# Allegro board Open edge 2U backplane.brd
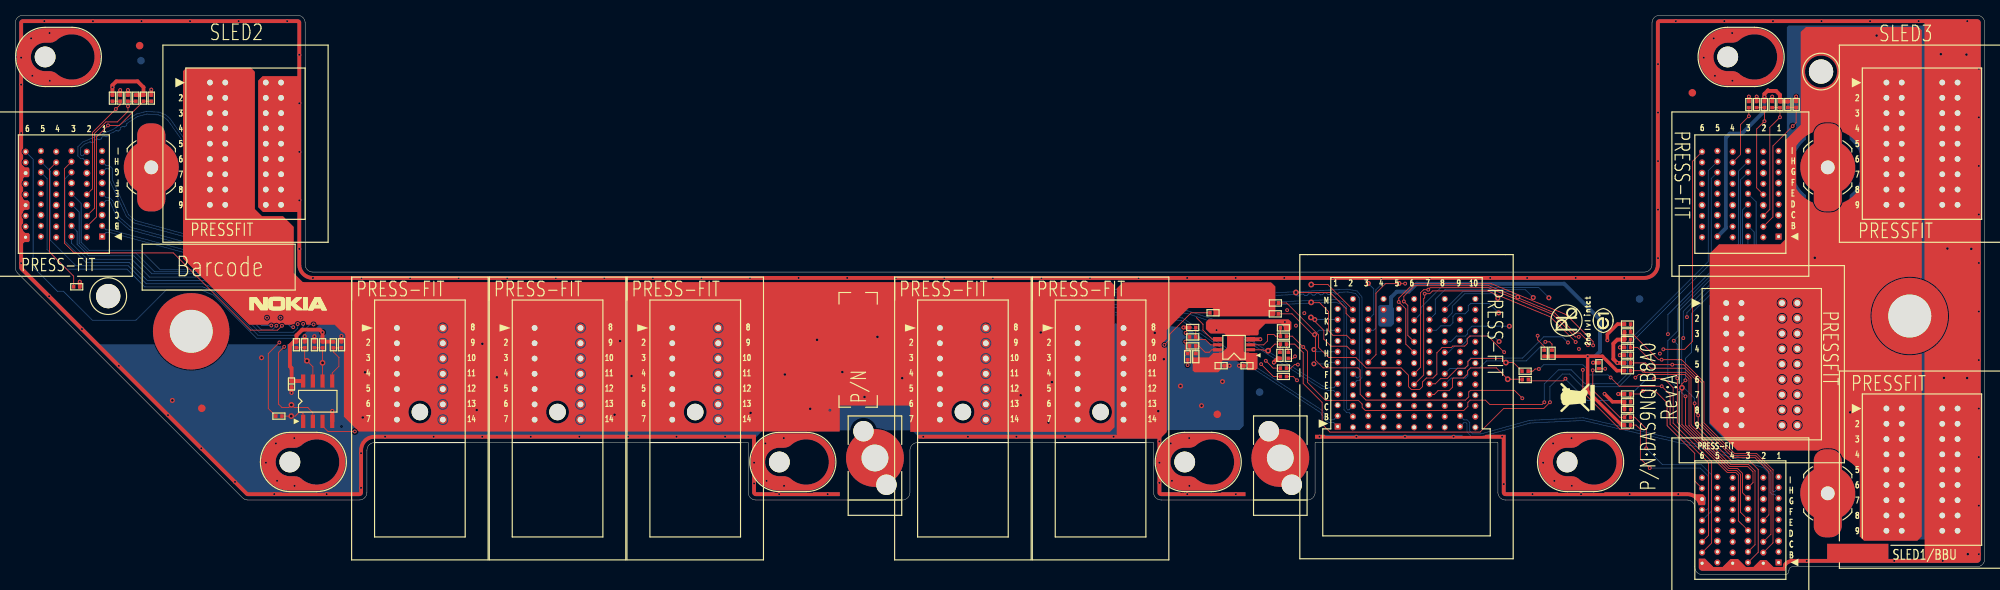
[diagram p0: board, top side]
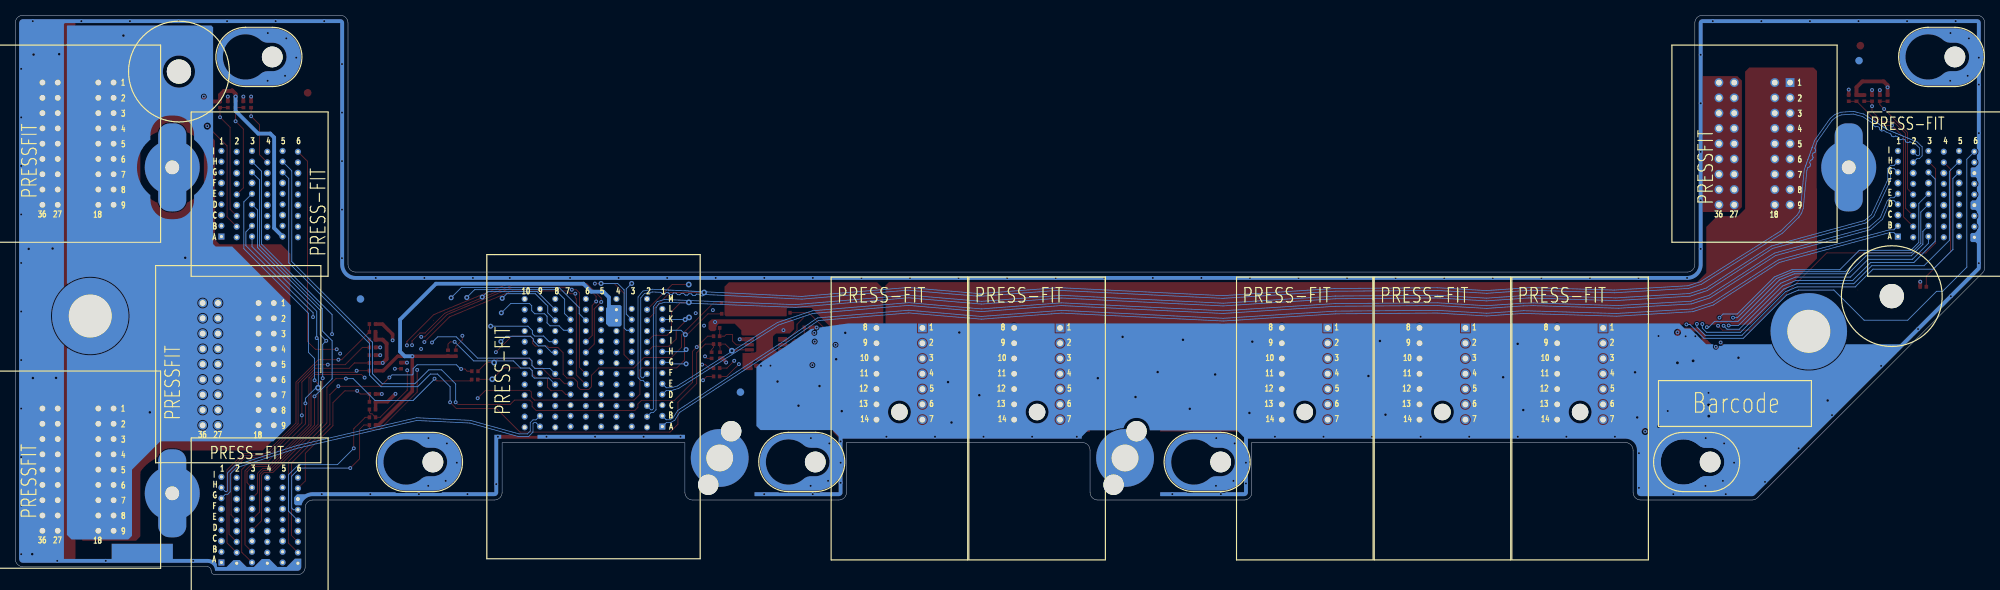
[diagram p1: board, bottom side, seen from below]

Outline 257.5 x 73.2 mm; copper layers: TOP, GND, IN1, VCC, VCC1, IN2, GND1, BOTTOM. Coordinates in mm from the lower left corner of the outline.
Outline path: 0,72.2 0,40.19 arc(0.08,39.81) 0.29,39.48 29.71,10.07 arc(30.03,9.85) 30.41,9.77 44.98,9.77 arc(45.68,10.07) 45.98,10.77 45.98,16.29 arc(46.27,17) 46.98,17.29 95.83,17.29 95.83,10.77 arc(96.12,10.07) 96.83,9.77 115.97,9.77 arc(116.68,10.07) 116.97,10.77 116.97,16.29 arc(117.27,17) 117.98,17.29 148.82,17.29 148.82,10.77 arc(149.12,10.07) 149.82,9.77 168.95,9.77 arc(169.66,10.07) 169.95,10.77 169.95,17.28 193.85,17.28 193.85,10.77 arc(194.14,10.07) 194.85,9.77 218.6,9.77 arc(219.31,9.48) 219.6,8.77 219.6,1 arc(219.89,0.29) 220.6,0 231.4,0 arc(231.75,0.15) 231.9,0.5 231.9,0.55 arc(232.05,0.9) 232.4,1.05 256.5,1.05 arc(257.21,1.34) 257.5,2.05 257.5,72.2 arc(257.21,72.91) 256.5,73.2 215,73.2 arc(214.29,72.91) 214,72.2 214,40.6 arc(213.71,39.89) 213,39.6 38.9,39.6 arc(38.19,39.89) 37.9,40.6 37.9,72.2 arc(37.61,72.91) 36.9,73.2 1,73.2 arc(0.29,72.91) 0,72.2

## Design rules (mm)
constraint set DEFAULT: min track width 0.114
net group RESET: nets IRQ_RMC_ALERT_N TP_BUF_EN
net group SMB_BBU_ALERT_N: nets SMB_BBU_ALERT_N SMB_BBU_ALERT_R_N
net group SMB_PMBUS_BBU_SCL: nets SMB_PMBUS_BBU_SCL SMB_PMBUS_SCL
net group SMB_PMBUS_BBU_SDA: nets SMB_PMBUS_BBU_SDA SMB_PMBUS_SDA
net group SMB_SLED_BUF_SDA: nets SMB_SLED_BUF_SDA SMB_SLED_BUF_SDA_R
net group LAN: nets LAN_SLED1_MDIN1 LAN_SLED1_MDIP1 LAN_SLED2_MDIN3 LAN_SLED2_MDIP3
net group P3V3_SLED1: nets P3V3_SLED1 SB_SLED1_ADDR_0 SB_SLED1_ADDR_1 SB_SLED1_ADDR_2
net group P3V3_SLED2: nets P3V3_SLED2 SB_SLED2_ADDR_0 SB_SLED2_ADDR_1 SB_SLED2_ADDR_2
net group P3V3_SLED3: nets P3V3_SLED3 SB_SLED3_ADDR_0 SB_SLED3_ADDR_1 SB_SLED3_ADDR_2
net group SMB_SLED_BUF_SCL: nets SMB_SLED_BUF_SCL SMB_SLED_BUF_SCL_R SMB_SLED_BUF_SCL_R1
net group SMB_SLED_COMBINE_SCL: nets SMB_3UBP_TEMP_SCL SMB_SLED_COMBINE_SCL SMB_SLED_COMBINE_SCL_R SMB_SLED_COMBINE_SCL_R1
net group SMB_SLED_COMBINE_SDA: nets SMB_3UBP_TEMP_SDA SMB_SLED_COMBINE_SDA SMB_SLED_COMBINE_SDA_R SMB_SLED_COMBINE_SDA_R1

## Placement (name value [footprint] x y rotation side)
C1045  0.1UF  [C0402]  36.12 24.96 270 top
C1375  0.1UF  [C0402]  157.66 27.35 0 top
C1377  0.1UF  [C0402]  161.05 27.34 180 top
DM2  -  [WEEE]  206.52 21.52 90 top
DM3  -  [PB-E1_SMALL]  202.82 33.26 90 top
DM4  -  [PNLABEL_15X5]  112.7 21.92 90 top
DM6  -  [PCB_VENDOR_LOGO_15X8]  106.51 21.53 90 top
DM7  -  [BARCODE_20X6]  42.66 19.4 180 bottom
DM8  -  [BARCODE_20X6]  16.59 37.24 0 top
H1  -  [HOLE_C10D5-6B10_NPB]  247.7 33.85 0 top
H2  -  [HOLE_C10D5-6B10_NPB]  23 31.85 0 top
H5  -  [HOLE_C7-5D2-7_4-9B7-5_OB3-5XC3-75N_NPM]  3.9 67.75 90 top
H6  -  [HOLE_C7-5D2-7_4-9B7-5_OB3-5XC3-75N_NPM]  35.9 14.75 90 top
H9  -  [HOLE_C7-5D2-7_4-9B7-5_OB3-5XC3-75N_NPM]  223.9 67.75 90 top
H10  -  [HOLE_C7-5D2-7_4-9B7-5_OB3-5XC3-75N_NPM]  99.9 14.75 90 top
H11  -  [HOLE_C7-5D2-7_4-9B7-5_OB3-5XC3-75N_NPM]  152.9 14.75 90 top
H12  -  [HOLE_C7-5D2-7_4-9B7-5_OB3-5XC3-75N_NPM]  202.9 14.75 90 top
H13  -  [HOLE_TOOLINGD125N_T2-0]  12.15 36.45 0 top
H14  -  [HOLE_TOOLINGD125N_T2-0]  236.1 65.83 0 top
J2  -  [HSD_F36D9_P2_LUV]  244.65 21.75 0 top
J3  -  [HSD_F36D9_P2_LUV]  223.7 35.55 0 top
J4  -  [HSD_F36D9_P2_LUV]  25.45 64.4 0 top
J5  -  [HSD_F36D9_P2_LUV]  244.65 64.4 0 top
J7  -  [HSD_F54D6_P2W1-4_RDH]  230.55 1.6 180 top
J8  -  [HSD_M120D10H5D_P2W1-4_LDH]  172.9 19.39 180 top
J9  -  [HSD_F54D6_P2W1-4_RDH]  11.35 44.25 180 top
J10  -  [HSD_F54D6_P2W1-4_RDH]  230.55 44.25 180 top
J37  -  [CON_GUIDE-M1XE]  17.78 53.3 0 top
J39  -  [CON_GUIDE-M1XE]  236.98 10.65 0 top
J40  -  [CON_GUIDE-M1XE]  236.98 53.3 0 top
JP1  -  [HSD_M14]  85.9 32.29 0 top
JP2  -  [HSD_M14]  120.9 32.29 0 top
JP3  -  [HSD_M14]  67.9 32.29 0 top
JP4  -  [HSD_M14]  138.9 32.29 0 top
JP5  -  [CON_GUIDE-FXC]  112.4 15.28 0 top
JP6  -  [CON_GUIDE-FXC]  165.4 15.28 0 top
JP7  -  [HSD_M14]  49.9 32.29 0 top
NOREF  -  []  152.9 14.75 0 top
NOREF#2  -  []  0 72.2 0 top
NOREF#3  -  []  252.47 360.99 0 top
NOREF#4  -  []  152.9 14.75 0 top
NOREF#5  -  []  112.4 15.28 0 top
NOREF#6  -  []  23 31.85 0 top
NOREF#7  -  []  202.9 14.75 0 top
NOREF#8  -  []  322.16 7.18 0 top
NOREF#9  -  []  0 154 270 top
NOREF#10  -  []  202.9 14.75 0 top
NOREF#11  -  []  247.7 33.85 0 top
NOREF#12  -  []  236.98 10.65 0 top
NOREF#13  -  []  236.98 53.3 0 top
NOREF#14  -  []  0 160 0 top
NOREF#15  -  []  257.5 -5.6 270 top
NOREF#16  -  []  223.9 67.75 0 top
NOREF#17  -  []  3.9 67.75 0 top
NOREF#18  -  []  257.5 154 270 top
NOREF#19  -  []  17.78 53.3 0 top
NOREF#20  -  []  255.5 -13.6 90 top
NOREF#21  -  []  0 0 0 top
NOREF#22  -  [unnamed#2]  16.26 69.23 0 top
NOREF#23  -  [unnamed#2]  157.16 20.99 0 top
NOREF#24  -  [unnamed#2]  219.27 63.06 0 top
NOREF#25  -  []  236.98 10.65 0 top
NOREF#26  -  []  0 -5.6 270 top
NOREF#27  -  []  99.9 14.75 0 top
NOREF#28  -  []  165.4 15.28 0 top
NOREF#29  -  [unnamed#2]  24.38 21.77 0 top
NOREF#30  -  []  99.9 14.75 0 top
NOREF#31  -  []  23 31.85 0 top
NOREF#32  -  []  236.98 53.3 0 top
NOREF#33  -  []  17.78 53.3 0 top
NOREF#34  -  []  247.7 33.85 0 top
NOREF#35  -  []  165.4 15.28 0 top
NOREF#36  -  []  0 0 0 top
NOREF#37  -  []  223.9 67.75 0 top
NOREF#38  -  []  3.9 67.75 0 top
NOREF#39  -  []  231.4 0 90 top
NOREF#40  -  [unnamed#2]  212.37 36.07 180 bottom
NOREF#41  -  [unnamed#2]  162.69 23.89 180 bottom
NOREF#42  -  [unnamed#2]  16.43 67.26 180 bottom
R1  4.7K  [R0402]  15.75 62.36 270 top
R2  4.7K  [R0402]  228.7 61.52 270 top
R3  33  [R0402]  166.45 28.71 270 top
R4  33  [R0402]  165.81 25.94 0 top
R5  33  [R0402]  165.81 27.03 0 top
R8  4.7K  [R0402]  16.76 62.36 270 top
R9  1K  [R0402]  17.78 62.36 90 top
R10  4.7K  [R0402]  231.76 61.53 270 top
R11  1K  [R0402]  232.85 61.53 90 top
R12  4.7K  [R0402]  230.73 61.52 270 top
R13  4.7K  [R0402]  210.8 30.76 0 top
R14  4.7K  [R0402]  12.7 62.36 270 top
R15  4.7K  [R0402]  210.8 27.71 0 top
R19  1K  [R0402]  14.73 62.36 90 top
R20  1K  [R0402]  229.71 61.52 90 top
R21  1K  [R0402]  210.8 29.74 180 top
R22  1K  [R0402]  13.72 62.36 90 top
R23  1K  [R0402]  227.68 61.52 90 top
R24  1K  [R0402]  210.8 28.73 180 top
R29  4.7K  [R0402]  210.8 19.58 0 top
R31  4.7K  [R0402]  210.8 22.63 0 top
R32  1K  [R0402]  210.8 23.65 180 top
R34  4.7K  [R0402]  200.92 28.98 90 top
R35  4.7K  [R0402]  199.91 28.98 90 top
R36  4.7K  [R0402]  210.8 26.7 0 top
R37  4.7K  [R0402]  210.8 21.62 0 top
R38  0  [R0402]  210.8 20.6 0 top
R39  33  [R0402]  197.43 25.53 0 top
R40  33  [R0402]  197.41 26.63 0 top
R41  100  [R0402]  164.74 34.13 180 top
R42  100  [R0402]  156.6 34.28 0 top
R43  100  [R0402]  164.76 35.56 180 top
R46  0  [R0402]  153.95 29.94 0 top
R47  33  [R0402]  153.95 31.12 0 top
R48  4.7K  [R0402]  154.35 28.53 90 top
R49  4.7K  [R0402]  153.95 32.35 0 top
R50  4.7K  [R0402]  165.35 28.71 90 top
R51  4.7K  [R0402]  165.81 32.3 180 top
R52  33  [R0402]  165.81 30.17 0 top
R53  33  [R0402]  165.81 31.21 0 top
R54  0  [R0402]  207.07 27.35 90 top
R55  0  [R0402]  8.03 37.68 0 top
R56  0  [R0402]  226.67 61.52 90 top
R1102  4.7K  [R0402]  41.59 30.09 270 top
R1103  100  [R0402]  42.65 30.09 90 top
R1108  4.7K  [R0402]  40.17 30.09 270 top
R1109  100  [R0402]  39.11 30.09 90 top
R1113  4.7K  [R0402]  36.76 30.09 270 top
R1114  100  [R0402]  37.84 30.09 90 top
R1122  33.2  [R0402]  34.47 20.75 180 top
R1123  33.2  [R0402]  153.28 28.53 90 top
R2297  4.7K  [R0402]  210.8 31.78 0 top
R2298  1K  [R0402]  210.8 32.79 180 top
U31  -  [SOIC8]  39.54 22.7 90 top
U118  -  [TSSOP8_3XB]  159.35 29.76 180 top

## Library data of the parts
C1045 = Q_CAP: alternate symbols: (C0402_OCTAGONXA,C0402-0201); part number: Q_CAP_0402-0.1UF,25V,10%,X7R,CH4104K1B00; tolerance: 10%; signal model: DEFAULT_CAPACITOR_100000pF_2_1
C1375 C1377 = Q_CAP: alternate symbols: (C0402_OCTAGONXA,C0402-0201); part number: Q_CAP_0402-0.1UF,25V,10%,X7R,CH4104K1B00; tolerance: 10%
DM2 = DUMMY_SYMBOL: part number: DUMMY_SYMBOL-WEEE,MECH,EMPTY,DUMMY2
DM3 = DUMMY_SYMBOL: part number: DUMMY_SYMBOL-PB-E1_SMALL,MECH,EMPTY,DUMMY3
DM4 = DUMMY_SYMBOL: part number: DUMMY_SYMBOL-PCBA_LABEL_15X5,MECH,MECH,DUMMY4
DM6 = DUMMY_SYMBOL: part number: DUMMY_SYMBOL-PCB_VENDOR_LOGO_15X8,MECH,EMPTY,DUMMY7
DM7 DM8 = DUMMY_SYMBOL: part number: DUMMY_SYMBOL-BARCODE_20X6,MECH,MECH,DUMMY15
H1 H2 = HOLE: part number: HOLE_TH-EMPTY,HOLE596
H5 H6 H9-H12 = HOLE: part number: HOLE_TH-EMPTY,HOLE1056
H13 H14 = HOLE: part number: HOLE_TH-EMPTY,DUMMY50
J2-J5 = CONN36_10078768001LHLF: part number: CONN36_10078768001LHLF-CONN36_10078768-001LHLF,THLF,IO,DFHS36FS123
J7 J9 J10 = CONN54_10130665102LF: part number: CONN54_10130665102LF-CONN54_10130665-102LF,THLF,IO,DFHS54FS008
J8 = CONN120_10124150102LF: part number: CONN120_10124150102LF-CONN120_10124150-102LF,THLF,IO,DFHDC0MR005
J37 J39 J40 = CONN1_D11402200000Z1: part number: CONN1_D11402200000Z1-CONN1_D11402-200000-Z1,THLF,IO,DFHD01MS073
JP1-JP4 JP7 = CONN14_10028918001LF: part number: CONN14_10028918001LF-CONN14_10028918001LF,THLF,IO,DFPJ14MR000
JP5 JP6 = CONN1_D11403000A00Z1: part number: CONN1_D11403000A00Z1-CONN1_D11403-000A00-Z1,THLF,IO,DFHS03FR014
R1 R10 R12 R29 R34-R37 R1102 R1108 R2297 = Q_RES: alternate symbols: (R0402-0201); part number: Q_RES_0402LF-4.7K,1%,1/16W,CHIP,CS24702FB10; tolerance: 1%; signal model: DEFAULT_RESISTOR_4700OHM_2_1
R2 R8 R13-R15 R31 R1113 = Q_RES: alternate symbols: (R0402-0201); part number: Q_RES_0402LF-4.7K,1%,1/16W,EMPTY,CS24702FB10; tolerance: 1%; signal model: DEFAULT_RESISTOR_4700OHM_2_1
R3-R5 = Q_RES: alternate symbols: (R0402-0201); part number: Q_RES_0402LF-33       ,1%  ,1/16W,CHIP,CS03302FB19; tolerance: 1%; signal model: Q_RES_0402LF-33________1%___1/A_33
R9 R21-R24 R32 = Q_RES: alternate symbols: (R0402-0201); part number: Q_RES_0402LF-1K,1%,1/16W,CHIP,TMP_QCS21002FB24; tolerance: 1%; signal model: DEFAULT_RESISTOR_1000.000000OHM_2_1
R11 R19 R20 R2298 = Q_RES: alternate symbols: (R0402-0201); part number: Q_RES_0402LF-1K,1%,1/16W,EMPTY,TMP_QCS21002FB24; tolerance: 1%; signal model: DEFAULT_RESISTOR_1000.000000OHM_2_1
R38 = Q_RES: alternate symbols: (R0402-0201); part number: Q_RES_0402LF-0,5%,1/16W,CHIP,CS00002JB38; tolerance: 5%; signal model: DEFAULT_RESISTOR_0.001OHM_2_1
R39 R40 = Q_RES: alternate symbols: (R0402-0201); part number: Q_RES_0402LF-33       ,1%  ,1/16W,CHIP,CS03302FB19; tolerance: 1%; signal model: DEFAULT_RESISTOR_0.001OHM_2_1
R41-R43 = Q_RES: alternate symbols: (R0402-0201); part number: Q_RES_0402LF-100,1%,1/16W,CHIP,TMP_QCS11002FB22; tolerance: 1%
R46 = Q_RES: alternate symbols: (R0402-0201); part number: Q_RES_0402LF-0,5%,1/16W,CHIP,CS00002JB38; tolerance: 5%; signal model: Q_RES_0402LF-0_5%_1/16W_CHIP_CA_0
R47 R52 R53 = Q_RES: alternate symbols: (R0402-0201); part number: Q_RES_0402LF-33       ,1%  ,1/16W,CHIP,CS03302FB19; tolerance: 1%; signal model: Q_RES_0402LF-0_5%_1/16W_CHIP_CA_0
R48 R49 = Q_RES: alternate symbols: (R0402-0201); part number: Q_RES_0402LF-4.7K,1%,1/16W,EMPTY,CS24702FB10; tolerance: 1%
R50 R51 = Q_RES: alternate symbols: (R0402-0201); part number: Q_RES_0402LF-4.7K,1%,1/16W,CHIP,CS24702FB10; tolerance: 1%
R54-R56 = Q_RES: alternate symbols: (R0402-0201); part number: Q_RES_0402LF-0,5%,1/16W,CHIP,CS00002JB38; tolerance: 5%
R1103 R1109 = Q_RES: alternate symbols: (R0402-0201); part number: Q_RES_0402LF-100,1%,1/16W,EMPTY,TMP_QCS11002FB22; tolerance: 1%; signal model: DEFAULT_RESISTOR_100OHM_2_1
R1114 = Q_RES: alternate symbols: (R0402-0201); part number: Q_RES_0402LF-100,1%,1/16W,CHIP,TMP_QCS11002FB22; tolerance: 1%; signal model: DEFAULT_RESISTOR_100OHM_2_1
R1122 R1123 = Q_RES: alternate symbols: (R0402-0201); part number: Q_RES_0402LF-33.2,1%,1/16W,CHIP,CS03322FB34; tolerance: 1%; signal model: Q_RES_0402LF-33.2_1%_1/16W_CHIA_33.2
U31 = TMP75AIDR: part number: TMP75AIDR-TMP75AIDR,SMLF,IC,AL000075061
U118 = PCA9617ADP: part number: PCA9617ADP-PCA9617ADP,SMLF,IC,AL009617K02

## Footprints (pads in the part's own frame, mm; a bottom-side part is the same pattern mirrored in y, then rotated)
BARCODE_20X6
  round 0.102 smd: 1(0,0)
C0402
  rect 0.457x0.508 smd: 1(-0.4,0) 2(0.4,0)
CON_GUIDE-FXC
  round 2.667 hole 2.667 unplated: (-1.5,3.5) (1.5,-3.5)
  round 7.569 hole 3.505: SCR_G1(0,0)
CON_GUIDE-M1XE
  custom 1.798x1.798 hole 5.182: G1(0,0)
HOLE_C7-5D2-7_4-9B7-5_OB3-5XC3-75N_NPM
  round 2.718 hole 2.718 unplated: (0,0)
HOLE_C10D5-6B10_NPB
  round 10.008 hole 5.613: 1(0,0)
HOLE_TOOLINGD125N_T2-0
  round 3.175 hole 3.175 unplated: (0,0)
HSD_F36D9_P2_LUV
  rect 1.156x1.156 hole 0.75: 1(0,0)
  round 1.156 hole 0.75: 2(0,-2) 3(0,-4) 4(0,-6) 5(0,-8) 6(0,-10) 7(0,-12) 8(0,-14) 9(0,-16) 10(2,0) 11(2,-2) 12(2,-4) 13(2,-6) 14(2,-8) 15(2,-10) 16(2,-12) 17(2,-14) 18(2,-16) 19(7.3,0) 20(7.3,-2) 21(7.3,-4) 22(7.3,-6) 23(7.3,-8) 24(7.3,-10) 25(7.3,-12) 26(7.3,-14) 27(7.3,-16) 28(9.3,0) 29(9.3,-2) 30(9.3,-4) 31(9.3,-6) 32(9.3,-8) 33(9.3,-10) 34(9.3,-12) 35(9.3,-14) 36(9.3,-16)
HSD_F54D6_P2W1-4_RDH
  rect 0.806x0.806 hole 0.4: A1(0,0)
  round 0.806 hole 0.4: A2(2,0.1) A3(4,0) A4(6,0.1) A5(8,0) A6(10,0.1) B1(0,-1.4) B2(2,-1.3) B3(4,-1.4) B4(6,-1.3) B5(8,-1.4) B6(10,-1.3) C2(2,-2.7) C4(6,-2.7) C6(10,-2.7) D1(0,-4.2) D3(4,-4.2) D5(8,-4.2) E1(0,-5.6) E2(2,-5.5) E3(4,-5.6) E4(6,-5.5) E5(8,-5.6) E6(10,-5.5) F2(2,-6.9) F4(6,-6.9) F6(10,-6.9) G1(0,-8.4) G3(4,-8.4) G5(8,-8.4) H1(0,-9.8) H2(2,-9.7) H3(4,-9.8) H4(6,-9.7) H5(8,-9.8) H6(10,-9.7) I1(0,-11.2) I2(2,-11.1) I3(4,-11.2) I4(6,-11.1) I5(8,-11.2) I6(10,-11.1)
  round 0.906 hole 0.5: C1(0,-2.8) C3(4,-2.8) C5(8,-2.8) D2(2,-4.1) D4(6,-4.1) D6(10,-4.1) F1(0,-7) F3(4,-7) F5(8,-7) G2(2,-8.3) G4(6,-8.3) G6(10,-8.3)
HSD_M14
  round 2.159 hole 2.159 unplated: (3,-11)
  rect 1.156x1.156 hole 0.75: 1(0,0)
  round 1.156 hole 0.75: 2(0,-2) 3(0,-4) 4(0,-6) 5(0,-8) 6(0,-10) 7(0,-12) 8(6,0) 9(6,-2) 10(6,-4) 11(6,-6) 12(6,-8) 13(6,-10) 14(6,-12)
HSD_M120D10H5D_P2W1-4_LDH
  rect 0.8x0.8 hole 0.4: A1(0,0)
  round 0.8 hole 0.5: A2(-2,0.1) A4(-6,0.1) A6(-10,0.1) A8(-14,0.1) A10(-18,0.1) C1(0,-2.8) C3(-4,-2.8) C5(-8,-2.8) C7(-12,-2.8) C9(-16,-2.8) D2(-2,-4.1) D4(-6,-4.1) D6(-10,-4.1) D8(-14,-4.1) D10(-18,-4.1) F1(0,-7) F3(-4,-7) F5(-8,-7) F7(-12,-7) F9(-16,-7) G2(-2,-8.3) G4(-6,-8.3) G6(-10,-8.3) G8(-14,-8.3) G10(-18,-8.3) I1(0,-11.2) I3(-4,-11.2) I5(-8,-11.2) I7(-12,-11.2) I9(-16,-11.2) J2(-2,-12.5) J4(-6,-12.5) J6(-10,-12.5) J8(-14,-12.5) J10(-18,-12.5) L1(0,-15.4) L3(-4,-15.4) L5(-8,-15.4) L7(-12,-15.4) L9(-16,-15.4) MG1(-2,-16.7) MG2(-6,-16.7) MG3(-10,-16.7) MG4(-14,-16.7) MG5(-18,-16.7)
  round 0.8 hole 0.4: A3(-4,0) A5(-8,0) A7(-12,0) A9(-16,0) B1(0,-1.4) B2(-2,-1.3) B3(-4,-1.4) B4(-6,-1.3) B5(-8,-1.4) B6(-10,-1.3) B7(-12,-1.4) B8(-14,-1.3) B9(-16,-1.4) B10(-18,-1.3) C2(-2,-2.7) C4(-6,-2.7) C6(-10,-2.7) C8(-14,-2.7) C10(-18,-2.7) D1(0,-4.2) D3(-4,-4.2) D5(-8,-4.2) D7(-12,-4.2) D9(-16,-4.2) E1(0,-5.6) E2(-2,-5.5) E3(-4,-5.6) E4(-6,-5.5) E5(-8,-5.6) E6(-10,-5.5) E7(-12,-5.6) E8(-14,-5.5) E9(-16,-5.6) E10(-18,-5.5) F2(-2,-6.9) F4(-6,-6.9) F6(-10,-6.9) F8(-14,-6.9) F10(-18,-6.9) G1(0,-8.4) G3(-4,-8.4) G5(-8,-8.4) G7(-12,-8.4) G9(-16,-8.4) H1(0,-9.8) H2(-2,-9.7) H3(-4,-9.8) H4(-6,-9.7) H5(-8,-9.8) H6(-10,-9.7) H7(-12,-9.8) H8(-14,-9.7) H9(-16,-9.8) H10(-18,-9.7) I2(-2,-11.1) I4(-6,-11.1) I6(-10,-11.1) I8(-14,-11.1) I10(-18,-11.1) J1(0,-12.6) J3(-4,-12.6) J5(-8,-12.6) J7(-12,-12.6) J9(-16,-12.6) K1(0,-14) K2(-2,-13.9) K3(-4,-14) K4(-6,-13.9) K5(-8,-14) K6(-10,-13.9) K7(-12,-14) K8(-14,-13.9) K9(-16,-14) K10(-18,-13.9) L2(-2,-15.3) L4(-6,-15.3) L6(-10,-15.3) L8(-14,-15.3) L10(-18,-15.3)
PB-E1_SMALL
  round 0.102 smd: 1(0,0)
PCB_VENDOR_LOGO_15X8
  round 0.102 smd: 1(0,0)
PNLABEL_15X5
  round 0.102 smd: 1(0,0)
R0402
  rect 0.457x0.508 smd: 1(-0.4,0) 2(0.4,0)
SOIC8
  rect 1.727x0.559 smd: 1(-2.642,1.905) 2(-2.642,0.635) 3(-2.642,-0.635) 4(-2.642,-1.905) 5(2.642,-1.905) 6(2.642,-0.635) 7(2.642,0.635) 8(2.642,1.905)
TSSOP8_3XB
  rect 1.168x0.61 smd: 1(-2.175,1.05) 4(-2.175,-1.05) 5(2.175,-1.05) 8(2.175,1.05)
  rect 1.168x0.432 smd: 2(-2.175,0.325) 3(-2.175,-0.325) 6(2.175,-0.325) 7(2.175,0.325)
unnamed#2
  round 0.991 smd: 1(0,0)
WEEE
  round 0.102 smd: 1(0,0)

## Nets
GND: C1045.2(B) C1375.2(B) C1377.2(B) H1.1 H2.1 J2.19 J2.20 J2.21 J2.22 J2.23 J2.24 J2.25 J2.26 J2.27 J2.28 J2.29 J2.30 J2.31 J2.32 J2.33 J2.34 J2.35 J2.36 J3.19 J3.20 J3.21 J3.22 J3.23 J3.24 J3.25 J3.26 J3.27 J3.28 J3.29 J3.30 J3.31 J3.32 J3.33 J3.34 J3.35 J3.36 J4.19 J4.20 J4.21 J4.22 J4.23 J4.24 J4.25 J4.26 J4.27 J4.28 J4.29 J4.30 J4.31 J4.32 J4.33 J4.34 J4.35 J4.36 J5.19 J5.20 J5.21 J5.22 J5.23 J5.24 J5.25 J5.26 J5.27 J5.28 J5.29 J5.30 J5.31 J5.32 J5.33 J5.34 J5.35 J5.36 J7.A2 J7.A4 J7.A6 J7.C1 J7.C3 J7.C5 J7.D2 J7.D4 J7.D6 J7.F1 J7.F3 J7.F5 J7.G2 J7.G4 J7.G6 J7.I1 J7.I3 J7.I5 J8.A2 J8.A4 J8.A6 J8.A8 J8.A10 J8.C1 J8.C3 J8.C5 J8.C7 J8.C9 J8.D2 J8.D4 J8.D6 J8.D8 J8.D10 J8.F1 J8.F3 J8.F5 J8.F7 J8.F9 J8.G2 J8.G4 J8.G6 J8.G8 J8.G10 J8.I1 J8.I3 J8.I5 J8.I7 J8.I9 J8.J2 J8.J4 J8.J6 J8.J8 J8.J10 J8.L1 J8.L3 J8.L5 J8.L7 J8.L9 J8.MG1 J8.MG2 J8.MG3 J8.MG4 J8.MG5 J9.A2 J9.A4 J9.A6 J9.C1 J9.C3 J9.C5 J9.D2 J9.D4 J9.D6 J9.F1 J9.F3 J9.F5 J9.G2 J9.G4 J9.G6 J9.I1 J9.I3 J9.I5 J10.A2 J10.A4 J10.A6 J10.C1 J10.C3 J10.C5 J10.D2 J10.D4 J10.D6 J10.F1 J10.F3 J10.F5 J10.G2 J10.G4 J10.G6 J10.I1 J10.I3 J10.I5 J37.G1 J39.G1 J40.G1 JP1.8 JP1.9 JP1.10 JP1.11 JP1.12 JP1.13 JP1.14 JP2.8 JP2.9 JP2.10 JP2.11 JP2.12 JP2.13 JP2.14 JP3.8 JP3.9 JP3.10 JP3.11 JP3.12 JP3.13 JP3.14 JP4.8 JP4.9 JP4.10 JP4.11 JP4.12 JP4.13 JP4.14 JP5.SCR_G1 JP6.SCR_G1 JP7.8 JP7.9 JP7.10 JP7.11 JP7.12 JP7.13 JP7.14 R9.2(B) R11.2(B) R19.2(B) R20.2(B) R21.2(B) R22.2(B) R23.2(B) R24.2(B) R32.2(B) R41.2(B) R42.2(B) R43.2(B) R54.2(B) R55.2(B) R56.2(B) R1103.2(B) R1109.2(B) R1114.2(B) R2298.2(B) U31.4 U118.4
P3V3_RMC_STBY: C1045.1 C1375.1 C1377.1 J8.K4 J8.L4 R29.1 R31.1 R34.1 R35.1 R36.1 R37.1 R48.1 R49.1 R50.1 R51.1 R1102.1 R1108.1 R1113.1 U31.8(VCC) U118.1 U118.8(VCCB)
P3V3_SLED1: J7.A5 R13.1 R15.1 R2297.1
P3V3_SLED2: J9.A5 R1.1 R8.1 R14.1
P3V3_SLED3: J10.A5 R2.1 R10.1 R12.1
P12V_PSU: J2.1 J2.2 J2.3 J2.4 J2.5 J2.6 J2.7 J2.8 J2.9 J2.10 J2.11 J2.12 J2.13 J2.14 J2.15 J2.16 J2.17 J2.18 J3.1 J3.2 J3.3 J3.4 J3.5 J3.6 J3.7 J3.8 J3.9 J3.10 J3.11 J3.12 J3.13 J3.14 J3.15 J3.16 J3.17 J3.18 J4.1 J4.2 J4.3 J4.4 J4.5 J4.6 J4.7 J4.8 J4.9 J4.10 J4.11 J4.12 J4.13 J4.14 J4.15 J4.16 J4.17 J4.18 J5.1 J5.2 J5.3 J5.4 J5.5 J5.6 J5.7 J5.8 J5.9 J5.10 J5.11 J5.12 J5.13 J5.14 J5.15 J5.16 J5.17 J5.18 JP1.1 JP1.2 JP1.3 JP1.4 JP1.5 JP1.6 JP1.7 JP2.1 JP2.2 JP2.3 JP2.4 JP2.5 JP2.6 JP2.7 JP3.1 JP3.2 JP3.3 JP3.4 JP3.5 JP3.6 JP3.7 JP4.1 JP4.2 JP4.3 JP4.4 JP4.5 JP4.6 JP4.7 JP7.1 JP7.2 JP7.3 JP7.4 JP7.5 JP7.6 JP7.7
FM_BBU_PRSNT_N: J7.F6 J8.B7 R29.2(B)
FM_BMC_SLED1_READY_N: J7.H3 J8.C8
FM_BMC_SLED2_READY_N: J8.H3 J9.H3
FM_BMC_SLED3_READY_N: J8.F8 J10.H3
FM_RMC_GPIO_0: J7.D3 J8.F6 J9.D3 J10.D3
FM_RMC_GPIO_1: J7.E3 J8.H6 J9.E3 J10.E3
FM_RMC_GPIO_2: J7.G3 J8.I6 J9.G3 J10.G3
FM_SLED1_PRSNT_N: J7.B3 J8.B8 R36.2(B)
FM_SLED2_PRSNT_N: J8.G3 J9.B3 R35.2(B)
FM_SLED3_PRSNT_N: J8.E8 J10.B3 R34.2(B)
IRQ_RMC_ALERT_N: J7.A3 J8.E6 J9.A3 J10.A3
LAN_SLED1_MDIN0: J7.B1 J8.C10
LAN_SLED1_MDIN1: J7.E1 J8.E10
LAN_SLED1_MDIN2: J7.H1 J8.B9
LAN_SLED1_MDIN3: J7.I2 J8.E9
LAN_SLED1_MDIP0: J7.A1 J8.B10
LAN_SLED1_MDIP1: J7.D1 J8.F10
LAN_SLED1_MDIP2: J7.G1 J8.A9
LAN_SLED1_MDIP3: J7.H2 J8.D9
LAN_SLED2_MDIN0: J8.B1 J9.B1
LAN_SLED2_MDIN1: J8.E1 J9.E1
LAN_SLED2_MDIN2: J8.C2 J9.H1
LAN_SLED2_MDIN3: J8.F2 J9.I2
LAN_SLED2_MDIP0: J8.A1 J9.A1
LAN_SLED2_MDIP1: J8.D1 J9.D1
LAN_SLED2_MDIP2: J8.B2 J9.G1
LAN_SLED2_MDIP3: J8.E2 J9.H2
LAN_SLED3_MDIN0: J8.K10 J10.B1
LAN_SLED3_MDIN1: J8.H10 J10.E1
LAN_SLED3_MDIN2: J8.H9 J10.H1
LAN_SLED3_MDIN3: J8.J9 J10.I2
LAN_SLED3_MDIP0: J8.L10 J10.A1
LAN_SLED3_MDIP1: J8.I10 J10.D1
LAN_SLED3_MDIP2: J8.G9 J10.G1
LAN_SLED3_MDIP3: J8.K9 J10.H2
PD_BBU_A0: J7.H6 R31.2(B) R32.1
PD_SLED1_CHASSIS_INTRUSION: J7.H4 R54.1
PD_SLED1_PRSNT_RETURN: J7.I6 R41.1
PD_SLED2_CHASSIS_INTRUSION: J9.H4 R55.1
PD_SLED2_PRSNT_RETURN: J9.I6 R42.1
PD_SLED3_CHASSIS_INTRUSION: J10.H4 R56.1
PD_SLED3_PRSNT_RETURN: J10.I6 R43.1
SB_SLED1_ADDR_0: J7.B2 R2297.2(B) R2298.1
SB_SLED1_ADDR_1: J7.C2 R13.2(B) R21.1
SB_SLED1_ADDR_2: J7.E2 R15.2(B) R24.1
SB_SLED2_ADDR_0: J9.B2 R8.2(B) R9.1
SB_SLED2_ADDR_1: J9.C2 R1.2(B) R19.1
SB_SLED2_ADDR_2: J9.E2 R14.2(B) R22.1
SB_SLED3_ADDR_0: J10.B2 R10.2(B) R11.1
SB_SLED3_ADDR_1: J10.C2 R12.2(B) R20.1
SB_SLED3_ADDR_2: J10.E2 R2.2(B) R23.1
SMB_3UBP_TEMP_SCL: R1123.1 U31.2
SMB_3UBP_TEMP_SDA: R1122.1 U31.1
SMB_BBU_ALERT_N: J8.A7 R37.2(B) R38.1
SMB_BBU_ALERT_R_N: J7.E6 R38.2(B)
SMB_PMBUS_BBU_SCL: J7.B6 R39.2(B)
SMB_PMBUS_BBU_SDA: J7.C6 R40.2(B)
SMB_PMBUS_SCL: J8.D7 R39.1
SMB_PMBUS_SDA: J8.E7 R40.1
SMB_SLED_BUF_SCL: J7.G5 J10.G5 R3.1 R52.2(B)
SMB_SLED_BUF_SCL_R: R50.2(B) R52.1 U118.2
SMB_SLED_BUF_SCL_R1: J9.G5 R3.2(B)
SMB_SLED_BUF_SDA: J7.H5 J9.H5 J10.H5 R53.2(B)
SMB_SLED_BUF_SDA_R: R51.2(B) R53.1 U118.3
SMB_SLED_COMBINE_SCL: R4.1 R46.1 R1123.2(B)
SMB_SLED_COMBINE_SCL_R: R46.2(B) R48.2(B) U118.7
SMB_SLED_COMBINE_SCL_R1: J8.G5 R4.2(B)
SMB_SLED_COMBINE_SDA: R5.1 R47.1 R1122.2(B)
SMB_SLED_COMBINE_SDA_R: R47.2(B) R49.2(B) U118.6
SMB_SLED_COMBINE_SDA_R1: J8.H5 R5.2(B)
TMP75_1_A0: R1113.2(B) R1114.1 U31.7
TMP75_1_A1: R1108.2(B) R1109.1 U31.6
TMP75_1_A2: R1102.2(B) R1103.1 U31.5
TP_BUF_EN: U118.5
TP_FM_BMC_SLED4_READY_N: J8.K3
TP_FM_BMC_SLED5_READY_N: J8.I8
TP_FM_SLED4_PRSNT_N: J8.J3
TP_FM_SLED5_PRSNT_N: J8.H8
TP_LAN_SLED4_MDIN0: J8.H1
TP_LAN_SLED4_MDIN1: J8.K1
TP_LAN_SLED4_MDIN2: J8.I2
TP_LAN_SLED4_MDIN3: J8.L2
TP_LAN_SLED4_MDIP0: J8.G1
TP_LAN_SLED4_MDIP1: J8.J1
TP_LAN_SLED4_MDIP2: J8.H2
TP_LAN_SLED4_MDIP3: J8.K2
TP_LAN_SLED5_MDIN0: J8.K5
TP_LAN_SLED5_MDIN1: J8.K6
TP_LAN_SLED5_MDIN2: J8.K7
TP_LAN_SLED5_MDIN3: J8.L8
TP_LAN_SLED5_MDIP0: J8.J5
TP_LAN_SLED5_MDIP1: J8.L6
TP_LAN_SLED5_MDIP2: J8.J7
TP_LAN_SLED5_MDIP3: J8.K8
TP_TMP75_1_ALERT: U31.3

Pads without a net: DM2 1; DM3 1; DM4 1; DM6 1; DM7 1; DM8 1; J7 B4 B5 C4 D5 E4 E5 F2 F4 I4; J8 A3 A5 B3 B4 B5 B6 C4 C6 D3 D5 E3 E4 E5 F4 G7 H4 H7 I4; J9 B4 B5 B6 C4 C6 D5 E4 E5 E6 F2 F4 F6 H6 I4; J10 B4 B5 B6 C4 C6 D5 E4 E5 E6 F2 F4 F6 H6 I4; NOREF#22 1; NOREF#23 1; NOREF#24 1; NOREF#29 1; NOREF#40 1; NOREF#41 1; NOREF#42 1

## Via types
v1: diameter 0.508, hole 0.254, TOP to BOTTOM, 244 vias
v2: diameter 0.66, hole 0.33, TOP to BOTTOM, 52 vias
v3: diameter 0.762, hole 0.381, TOP to BOTTOM, 12 vias

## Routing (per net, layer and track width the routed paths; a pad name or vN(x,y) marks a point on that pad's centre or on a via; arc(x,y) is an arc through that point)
GND: length 18.5
  TOP w0.457: v1(13.72,63.41) R22.2 ; R20.2 v1(229.71,62.56) ; R56.2 v1(226.67,62.56) ; R2298.2 209.49,32.79 208.16,31.46 v1(208.16,30.67) ; R32.2 v1(209.58,23.65) ; R21.2 v1(209.79,29.74) ; R23.2 v1(227.68,62.56) ; R24.2 v1(209.79,28.73) ; R19.2 v1(14.73,63.42) ; R9.2 v1(17.78,63.48)
  TOP w0.508: R1109.2 v1(39.11,31.2) ; v1(41.45,21.42) U31.4 ; R55.2 v1(8.43,38.34) ; C1377.2 v1(160,27.34) ; R11.2 v1(232.85,62.56) ; v1(42.65,31.23) R1103.2 ; U118.4 v1(162.79,30.81) ; C1045.2 v1(36.12,23.79) ; C1375.2 v1(158.76,27.35) ; R1114.2 v1(37.84,31.21) ; R54.2 v1(206.29,27.75)
  vias: v1(0.77,67.66) v1(0.77,64.13) v1(0.77,57.78) v1(0.77,40.76) v1(2.07,70.18) v1(2.23,65.28) v1(3.8,72.43) v1(4.42,36.44) v1(4.48,70.88) v1(4.51,64.63) v1(8.72,32.14) v1(10.15,72.43) v1(13.54,27.33) v1(16.5,72.43) v1(19.97,20.88) v1(22.85,72.43) v1(24.32,16.54) v1(28.72,12.15) v1(29.2,72.43) v1(32.77,14.66) v1(33.86,10.54) v1(34.07,17.18) v1(34.23,12.28) v1(35.55,72.43) v1(36.48,17.88) v1(36.51,11.63) v1(37.14,68.03) v1(37.14,61.68) v1(37.14,55.33) v1(37.14,48.98) v1(37.14,42.63) v1(38.92,38.83) v1(40.72,10.54) v1(45.21,15.91) v1(45.21,11.36) v1(45.27,38.83) v1(48.35,18.06) v1(51.62,38.83) v1(54.7,18.06) v1(57.97,38.83) v1(61.05,18.06) v1(64.32,38.83) v1(67.4,18.06) v1(70.67,38.83) v1(73.75,18.06) v1(77.02,38.83) v1(80.1,18.06) v1(83.37,38.83) v1(86.45,18.06) v1(89.72,38.83) v1(92.8,18.06) v1(96.07,38.83) v1(96.59,14.66) v1(96.59,11.94) v1(98.07,17.18) v1(98.23,12.28) v1(99.87,10.55) v1(100.48,17.88) v1(100.51,11.63) v1(102.42,38.83) v1(106.22,10.55) v1(108.77,38.83) v1(115.12,38.83) v1(118.71,18.06) v1(121.47,38.83) v1(124.55,18.06) v1(127.82,38.83) v1(130.9,18.06) v1(134.17,38.83) v1(137.25,18.06) v1(140.52,38.83) v1(143.6,18.06) v1(146.87,38.83) v1(149.59,17.44) v1(149.59,14.66) v1(149.59,12.03) v1(151.07,17.18) v1(151.23,12.28) v1(153.22,38.83) v1(153.23,10.54) v1(153.48,17.88) v1(153.51,11.63) v1(159.57,38.83) v1(159.58,10.54) v1(165.92,38.83) v1(170.52,18.06) v1(172.27,38.83) v1(175.35,18.06) v1(178.62,38.83) v1(181.7,18.06) v1(184.97,38.83) v1(188.05,18.06) v1(192.84,38.83) v1(194.4,18.06) v1(194.62,11.86) v1(197.67,38.83) v1(198.38,10.54) v1(199.77,14.66) v1(201.07,17.18) v1(201.23,12.28) v1(203.48,17.88) v1(203.51,11.63) v1(204.02,38.83) v1(204.44,29.54) v1(204.73,10.54) v1(210.37,38.83) v1(211.08,10.54) v1(214.78,66.82) v1(214.78,60.47) v1(214.78,54.12) v1(214.78,47.77) v1(214.78,41.42) v1(215.03,28.93) v1(217.11,72.43) v1(217.43,10.54) v1(220.77,67.66) v1(222.07,70.18) v1(222.23,65.28) v1(223.46,72.43) v1(224.48,70.88) v1(224.51,64.63) v1(229.81,72.43) v1(234.24,1.81) v1(236.16,72.43) v1(242.51,72.43) v1(245.67,1.81) v1(248.86,72.43) v1(252.02,1.81) v1(255.21,72.43) v1(256.73,66.19) v1(256.73,59.84) v1(256.73,53.49) v1(256.73,47.14) v1(256.73,40.79) v1(256.73,34.44) v1(256.73,28.09) v1(256.73,21.74) v1(256.73,15.39) v1(256.73,9.04) v1(256.73,2.69) v2(20.53,22.8) v2(32.19,28.39) v2(45.43,20.58) v2(45.72,26.49) v2(60.33,21.55) v2(61.06,30.21) v2(62.96,25.84) v2(78.35,20.94) v2(79.08,30.58) v2(80.58,26) v2(95.76,30.49) v2(96.14,21.17) v2(100.62,26.2) v2(103.94,21.71) v2(104.83,30.74) v2(108.14,26.52) v2(111.03,23.25) v2(112.72,31.12) v2(115.96,25.72) v2(131.46,23.49) v2(134.08,31.69) v2(135.09,19.92) v2(135.54,25.2) v2(148.98,31.65) v2(149.44,21.4) v2(150.17,28.2) v2(152.35,24.69) v2(155.1,22.12) v2(157.84,25.28) v2(251.77,68.11) v2(252.17,25.75) v2(252.63,42.68) v2(255.11,68.06) v2(255.2,25.73) v2(255.29,2.69) v2(255.74,42.63)
P3V3_RMC_STBY: length 244.3
  TOP w0.457: v1(207.79,23.67) 208.83,22.63 R31.1 R37.1 ; R35.1 R34.1 v1(205.59,28.58) ; v1(205.59,28.58) 207.51,28.58 209.4,26.7 R36.1 ; v1(205.59,28.58) 205.59,24.01 210.02,19.58 R29.1
  TOP w0.508: U31.8 36.13,25.34 C1045.1 36.12,27.04 35.9,27.25 35.9,29.99 36.41,30.49 R1113.1 36.76,31.32 37.51,32.06 39.82,32.06 v1(40.17,31.71) R1108.1 R1102.1 ; R51.1 166.21,32.87 v1(166.01,33.07) ; R49.1 v1(152.74,32.35) ; R50.1 165.06,28.31 164.56,27.8 v1(164.56,27.77)
  IN1 w0.508: v1(157.07,32) 158.13,33.07 v1(166.01,33.07)
  IN2 w0.508: v1(40.17,31.71) 46.2,37.74 150.68,37.74 152.74,35.69 v1(152.74,32.35) 156.71,32.35 v1(157.07,32) ; v1(207.79,23.67) 206.81,23.67 204.19,26.29 204.19,27.18 v1(205.59,28.58) ; J8.L4 178.46,34.68 176.13,37.01 169.96,37.01 v1(166.01,33.07) 165.86,32.92 165.86,29.08 v1(164.56,27.77)
  BOTTOM w0.508: J8.L4 179.37,34.68 179.89,35.2 179.89,36.3 180.62,37.04 182.18,37.04 183.22,38.07 202.5,38.07 207.19,33.38 207.19,29.2 206.58,28.58 v1(205.59,28.58)
P3V3_SLED1: length 40.8
  TOP w0.508: R15.1 v1(209.46,27.71) 208.95,28.23 208.95,30.24 209.46,30.76 R13.1 R2297.1
  IN1 w0.508: v1(209.46,27.71) 212.9,27.71 213.57,27.04 213.57,24.97 223.56,14.98 223.56,2.61 J7.A5
P3V3_SLED2: length 33.1
  TOP w0.508: R14.1 v1(12.7,63.77) 12.7,64.05 13.21,64.55 15.99,64.55 16.76,63.78 R8.1 R1.1
  IN1 w0.508: v1(12.7,63.77) 12.7,61.97 9.67,58.94 6.7,58.94 4.39,56.63 4.39,45.29 J9.A5
P3V3_SLED3: length 27.1
  TOP w0.508: R2.1 v1(228.7,62.56) 228.7,62.91 229.16,63.37 229.24,63.3 230.22,63.3 230.73,62.79 R12.1 231.76,61.92 R10.1
  BOTTOM w0.508: v1(228.7,62.56) 228.7,60.68 225.74,57.72 224.17,57.72 223.66,57.21 223.66,45.36 J10.A5
P12V_PSU:
  vias: v2(235.28,41.47) v2(239.91,21.25) v2(243.37,70.55)
FM_BBU_PRSNT_N: length 73.4
  TOP w0.114: v1(213.7,13.96) 212.48,15.18 212.48,19.01 211.91,19.58 R29.2 211.2,19.22 211.02,19.04 209.81,19.04 204.95,23.89 v1(204.95,26.8)
  IN1 w0.127: v1(204.95,26.8) 201.23,26.8 196.92,31.1 196.92,32.66 192.45,37.14 186.2,37.14 184.11,35.05 184.11,21.57 J8.B7
  BOTTOM w0.114: J7.F6 221.14,8.5 221.36,8.72 221.36,12.9 220.3,13.96 v1(213.7,13.96)
FM_BMC_SLED1_READY_N: length 53.6
  TOP w0.114: J7.H3 227.2,12.05 227.2,13.47 226.5,14.17 224.17,14.17 218.84,19.5 218.84,25.65 218.3,26.19 212.23,26.19 v1(211.83,25.79)
  IN1 w0.127: v1(211.83,25.79) 210.64,24.6 192.18,24.6 191.71,24.13 190.21,24.13 189.84,23.76 189.84,23.07 189.56,22.79 187.6,22.79 J8.C8
FM_BMC_SLED2_READY_N: length 192.2
  TOP w0.114: v1(34.87,32.58) 34.29,32 30.77,32 20.65,42.11 7.7,42.11 6.42,43.39 6.42,53.12 J9.H3
  IN1 w0.127: v1(34.87,32.58) 34.87,33.1 38.51,36.74 148.09,36.74 150.72,34.11 165.93,34.11 166.81,33.23 166.81,32.34 169.34,29.82 175.45,29.82 176.08,29.19 J8.H3
FM_BMC_SLED3_READY_N: length 60.8
  IN1 w0.127: v1(203.01,30.38) 205.49,32.86 212.88,32.86 214.76,30.98 215.59,30.98 v1(216.08,31.48)
  BOTTOM w0.114: J10.H3 225.3,52.8 225.3,43.26 216.08,34.05 v1(216.08,31.48) ; J8.F8 187.6,26.99 189.56,26.99 189.94,27.37 189.94,27.99 190.3,28.35 197.07,28.35 199.84,31.12 202.27,31.12 v1(203.01,30.38)
FM_RMC_GPIO_0: length 287
  TOP w0.114: v1(217.31,25.71) 217.31,19.9 223.84,13.37 224.96,13.37 225.29,13.03 225.29,7.06 J7.D3 ; v1(204.43,31.12) 203.95,31.12 201.01,34.07 192.59,37.55 185,37.55 v1(184.74,37.29) 184.14,37.29 183.73,36.88 183.73,27.12 J8.F6
  IN1 w0.127: v1(216.85,30.61) 214.35,30.61 212.71,32.25 205.55,32.25 v1(204.43,31.12) ; v1(184.74,37.29) 181.59,37.29 180.62,38.26 37.17,38.26 32.91,34 v1(32.91,33.63)
  BOTTOM w0.114: J9.D3 8.35,47.45 8.35,43.35 9.58,42.12 15.72,42.12 18.2,39.65 25.06,39.65 27.23,38.75 32.35,33.63 v1(32.91,33.63) ; v1(217.31,25.71) 217.31,30.15 v1(216.85,30.61) 217.62,31.39 217.62,34.61 225.83,42.82 225.83,47.73 J10.D3
FM_RMC_GPIO_1: length 287.4
  TOP w0.114: J7.E3 225.56,8.19 225.56,13.14 225.07,13.63 223.95,13.63 217.91,19.67 v3(217.91,24.46) 217.91,24.98 v1(218.37,25.44) ; v1(206.3,30.01) 206.3,30.51 202.77,34.04 192.99,38.09 182.78,38.09 180.89,36.2 v1(180.89,35.69) 181.81,34.77 181.81,30.18 J8.H6
  IN1 w0.127: v1(180.89,35.69) 179.51,37.07 38.11,37.07 v1(34.68,33.64) ; v1(218.37,25.44) 217.16,26.65 215.97,26.65 212.37,30.25 208.63,30.25 208.39,30.01 v1(206.3,30.01)
  BOTTOM w0.114: J9.E3 8.62,48.58 8.62,43.48 9.65,42.44 16.4,42.44 18.93,39.91 25.2,39.91 27.5,38.96 32.35,34.11 34.21,34.11 v1(34.68,33.64) ; J10.E3 227.62,48.78 227.62,42.67 219.17,34.21 219.17,29.09 218.37,28.3 v1(218.37,25.44)
FM_RMC_GPIO_2: length 294.4
  TOP w0.114: J7.G3 225.83,10.72 225.83,13.26 225.18,13.9 224.06,13.9 218.38,19.58 v1(218.38,23.34) ; J8.I6 182.07,31.31 182.07,35.24 v1(181.55,35.76) 181.55,36.43 182.94,37.82 192.65,37.82 201.33,34.22 203.93,31.62 204.58,31.62 205.62,30.58 v1(205.62,30.03)
  IN1 w0.127: v1(218.38,23.34) 215.61,26.1 215.61,26.44 212.81,29.24 206.41,29.24 205.62,30.02 v1(205.62,30.03) ; v1(181.55,35.76) 179.91,37.4 37.59,37.4 34.14,33.95 v1(34.14,32.58)
  BOTTOM w0.114: J9.G3 6.48,51.78 6.48,43.63 9.26,40.85 14.91,40.85 17.27,38.49 24.68,38.49 26.46,37.76 32.09,32.12 33.68,32.12 v1(34.14,32.58) ; J10.G3 225.56,51.66 225.56,43.03 217.36,34.82 217.36,31.9 216.07,30.61 216.07,25.64 v1(218.38,23.34)
FM_SLED1_PRSNT_N: length 65.3
  TOP w0.114: R36.2 v1(212.87,26.7) 213.08,26.48 218.38,26.48 219.11,25.76 219.11,19.61 224.28,14.43 226.61,14.43 227.47,13.58 227.47,3.92 J7.B3
  IN1 w0.127: v1(212.87,26.7) 212.87,26.08 211.05,24.27 193.17,24.27 191.76,22.86 190.28,22.86 189.89,22.47 189.89,22.06 189.41,21.58 187.79,21.58 J8.B8
FM_SLED2_PRSNT_N: length 220.4
  TOP w0.114: v1(181.72,38.09) 179.16,38.09 177.91,36.83 177.91,28.79 J8.G3 ; v1(199.04,31.27) 199.04,30.73 199.91,29.87 R35.2
  IN1 w0.127: v1(199.04,31.27) 199.04,31.92 192.87,38.09 v1(181.72,38.09) ; J8.G3 176.24,28.45 169.42,28.45 168.98,28.01 166.67,28.01 164.56,25.91 152.39,25.91 150.86,27.43 150.86,30.69 146.97,34.58 40.1,34.58 37.64,32.13 36.6,32.13 v1(36.34,32.39)
  BOTTOM w0.114: v1(36.34,32.39) 36.06,32.39 35.31,33.15 32.26,33.15 26.84,38.57 24.88,39.38 17.85,39.38 15.49,41.73 9.59,41.73 8.09,43.24 8.09,44.91 J9.B3
FM_SLED3_PRSNT_N: length 53.4
  TOP w0.114: R34.2 200.92,30.18 200.63,30.47 v1(200.06,30.47)
  IN1 w0.127: v1(200.06,30.47) 203.3,33.71 v1(218.57,33.71)
  BOTTOM w0.114: v1(218.57,33.71) 218.57,34.28 227.36,43.07 227.36,44.84 J10.B3 ; v1(200.06,30.47) 197.55,27.97 192.35,27.97 191.43,27.04 190.25,27.04 189.92,26.71 189.92,26.01 189.64,25.74 187.75,25.74 J8.E8
IRQ_RMC_ALERT_N: length 287.4
  TOP w0.114: J8.E6 184.15,26.13 184.15,36.12 184.28,36.25 v1(184.28,36.77) 184.94,36.77 185.3,37.13 192.51,37.13 200.73,33.73 v1(204.02,30.45) ; v1(219.57,22.42) 219.57,19.74 224.42,14.89 226.75,14.89 227.89,13.75 227.89,2.94 J7.A3
  IN1 w0.127: v1(218.09,30.96) 217.26,30.14 214.21,30.14 212.99,31.35 205.88,31.35 204.97,30.45 v1(204.02,30.45) ; v1(184.28,36.77) 181.5,36.77 180.44,37.83 37.39,37.83 33.47,33.92 v1(33.47,32.61)
  BOTTOM w0.114: J9.A3 7.35,43.37 9.45,41.27 15.24,41.27 17.56,38.95 24.72,38.95 26.67,38.14 32.2,32.61 v1(33.47,32.61) ; J10.A3 226.55,42.93 218.09,34.47 v1(218.09,30.96) 217.88,30.75 217.88,24.77 219.57,23.08 v1(219.57,22.42)
LAN_SLED1_MDIN0: length 52.4
  IN2 w0.114: J7.B1 230.06,2.51 229.88,2.51 229.74,2.65 229.74,13.7 229.03,14.42 217.23,18.67 210.6,20.19 208.08,20.59 203.31,21.09 193.73,21.6 191.39,21.6 J8.C10
LAN_SLED1_MDIN1: length 52.9
  IN2 w0.114: J8.E10 191.39,25.37 192.32,25.37 194.05,25.15 194.92,24.91 195.07,24.67 195.4,24.58 195.65,24.72 195.98,24.64 196.12,24.39 196.45,24.3 196.7,24.44 197.03,24.36 197.18,24.11 197.51,24.02 197.76,24.16 200.2,23.52 207.54,22.02 217.56,19.48 230.43,14.91 231.66,13.95 232.03,13.4 232.02,12.82 231.81,12.62 231.8,12.28 232,12.07 231.99,11.73 231.78,11.53 231.78,11.18 231.97,10.98 231.97,10.63 231.76,10.44 231.75,10.09 231.95,9.88 231.94,9.54 231.73,9.34 231.72,9 231.92,8.79 231.91,8.45 231.7,8.25 231.7,7.91 231.89,7.7 231.88,6.99 231.59,6.7 231.05,6.7 J7.E1
LAN_SLED1_MDIN2: length 47.4
  BOTTOM w0.099: J8.B9 189.42,20.26 189.81,20.26 190.17,19.91 190.17,18.8 190.55,18.43 191.63,18.43 198,20.2 205.02,20.54 220.77,16.87 228.76,14.31 229.75,13.32 229.75,10.99 229.86,10.88 230.03,10.88 J7.H1
LAN_SLED1_MDIN3: length 47.6
  IN2 w0.114: J7.I2 228.06,12.21 227.87,12.21 227.76,12.33 227.76,13.24 227.3,13.7 218.09,16.91 210.17,18.92 207.54,19.36 204.05,19.72 199.5,19.94 193.18,19.51 191.31,18.66 190.52,18.66 190.11,19.06 190.11,24.11 189.73,24.5 189.39,24.5 J8.E9
LAN_SLED1_MDIP0: length 52.5
  IN2 w0.114: J7.A1 230.06,2.09 229.7,2.09 229.32,2.47 229.32,13.52 228.79,14.05 217.11,18.26 210.52,19.77 208.03,20.17 203.28,20.67 193.72,21.17 191.39,21.17 J8.B10
LAN_SLED1_MDIP1: length 52.9
  IN2 w0.114: J7.D1 231.03,6.28 231.77,6.28 232.3,6.81 232.44,12.81 232.46,13.52 231.98,14.24 230.63,15.29 217.69,19.89 207.64,22.44 200.3,23.93 197.87,24.58 197.87,24.58 194.13,25.57 192.34,25.8 191.39,25.8 J8.F10
LAN_SLED1_MDIP2: length 47.4
  BOTTOM w0.099: J8.A9 189.42,19.91 189.67,19.91 189.82,19.76 189.82,18.66 190.4,18.07 191.68,18.07 198.06,19.85 204.99,20.18 220.67,16.53 228.57,14 229.4,13.17 229.4,10.84 229.72,10.52 230.03,10.52 J7.G1
LAN_SLED1_MDIP3: length 47.6
  IN2 w0.114: J7.H2 228.06,11.79 227.7,11.79 227.33,12.15 227.33,13.06 227.06,13.33 217.97,16.5 210.09,18.51 207.48,18.93 204.02,19.3 199.5,19.51 193.29,19.09 191.4,18.23 190.34,18.23 189.69,18.89 189.69,23.93 189.55,24.07 189.39,24.07 J8.D9
LAN_SLED2_MDIN0: length 168.8
  BOTTOM w0.099: J9.B1 11.87,45.13 12.45,45.13 27,41.18 35.61,35.62 38.22,34.77 48.15,34.18 60.3,34.55 65.1,34.21 71.59,34.59 84.85,34.49 99.57,33.55 120.69,34.59 131.16,33.79 140.67,34.61 152.62,33.6 156.98,30.59 170.9,21.48 171.53,20.47 171.89,20.28 172.39,20.28 J8.B1
LAN_SLED2_MDIN1: length 169.2
  BOTTOM w0.099: J8.E1 172.38,24.46 171.73,24.46 170.93,24.69 157.86,33 153.3,34.53 140.67,35.6 131.15,34.78 120.7,35.57 99.58,34.54 84.88,35.48 71.57,35.58 65.11,35.2 60.34,35.53 58.97,35.56 47.86,35.22 38.42,35.78 36.04,36.56 27.49,42.08 15.11,45.47 13.65,46.74 12.74,48.93 12.34,49.33 11.87,49.33 J9.E1
LAN_SLED2_MDIN2: length 185
  BOTTOM w0.099: J8.C2 174.38,21.56 174.24,21.56 174.08,21.72 174.08,35.05 173.57,35.73 172.62,36.01 155.5,35.34 140.7,36.59 131.15,35.77 120.71,36.56 99.58,35.53 84.92,36.46 84.91,36.46 71.56,36.56 71.54,36.56 65.11,36.19 59.64,36.57 48.22,36.22 38.59,36.79 36.42,37.5 27.89,43.01 15.71,46.34 14.81,47.09 12.67,51.69 12.67,53.16 12.31,53.53 11.87,53.53 J9.H1
LAN_SLED2_MDIN3: length 197.1
  BOTTOM w0.099: J8.F2 175.42,25.76 175.56,25.76 175.72,25.92 175.72,36.22 175.24,36.8 174.18,37 173.11,36.95 172.91,36.74 172.62,36.72 172.4,36.91 172.11,36.9 171.91,36.69 171.62,36.67 171.4,36.87 171.11,36.85 170.91,36.64 170.62,36.62 170.4,36.82 170.11,36.8 169.91,36.59 169.62,36.58 169.4,36.77 169.11,36.76 168.91,36.54 168.62,36.53 168.4,36.72 168.11,36.71 167.91,36.49 167.62,36.48 167.4,36.67 154.64,36.06 140.77,37.23 131.4,36.43 121.05,37.21 99.59,36.16 95.91,36.39 84.94,37.09 71.53,37.2 65.12,36.82 59.35,37.22 48.4,36.89 38.74,37.46 37.02,38.01 26.43,44.7 24.32,46.76 24.29,46.79 23.95,47.31 23.72,47.93 23.25,52.9 23.12,53.26 22.86,53.39 22.76,53.67 22.89,53.93 22.79,54.21 22.53,54.33 22.43,54.61 22.55,54.87 22.45,55.15 22.19,55.28 22.1,55.56 22.22,55.81 22.22,55.82 21.91,56.68 19.94,59.47 19.4,59.91 18.73,60.17 17.18,60.27 15.96,59.95 14.59,59.05 14.54,58.77 14.29,58.6 14.01,58.66 13.76,58.5 13.7,58.22 13.45,58.05 13.17,58.11 12.9,57.93 12.28,57.68 12.17,57.41 11.9,57.3 11.63,57.41 11.36,57.29 11.25,57.03 10.97,56.91 10.71,57.02 10.43,56.91 10.32,56.64 10.05,56.53 9.78,56.64 9.01,56.32 8.53,55.84 8.53,54.95 8.66,54.83 8.83,54.83 J9.I2
LAN_SLED2_MDIP0: length 168.8
  BOTTOM w0.099: J8.A1 172.36,19.92 171.8,19.92 171.28,20.21 170.64,21.23 156.79,30.3 152.5,33.25 140.67,34.25 131.16,33.44 121.98,34.13 120.68,34.23 99.57,33.2 84.84,34.14 71.6,34.24 65.1,33.86 60.29,34.19 48.15,33.83 38.16,34.42 35.46,35.3 26.85,40.86 12.4,44.77 11.87,44.77 J9.A1
LAN_SLED2_MDIP1: length 169.2
  BOTTOM w0.099: J9.D1 11.87,48.97 12.2,48.97 12.44,48.73 13.35,46.52 14.94,45.15 27.35,41.75 35.89,36.24 38.35,35.43 47.85,34.87 58.97,35.2 60.32,35.18 65.11,34.85 71.58,35.23 84.87,35.12 99.58,34.19 120.69,35.22 131.15,34.43 140.67,35.24 153.23,34.18 157.7,32.67 170.79,24.37 171.68,24.11 172.38,24.11 J8.D1
LAN_SLED2_MDIP2: length 185
  BOTTOM w0.099: J9.G1 11.87,53.17 12.16,53.17 12.32,53.02 12.32,51.61 12.35,51.54 14.53,46.87 15.54,46.02 27.74,42.69 36.26,37.18 38.52,36.44 48.21,35.87 59.63,36.21 65.11,35.83 71.55,36.21 84.91,36.11 92.23,35.64 99.58,35.17 120.71,36.21 131.15,35.42 140.7,36.23 155.49,34.99 172.58,35.66 173.36,35.42 173.72,34.93 173.72,21.58 174.09,21.21 174.38,21.21 J8.B2
LAN_SLED2_MDIP3: length 197
  BOTTOM w0.099: J8.E2 175.42,25.41 175.71,25.41 176.08,25.77 176.08,36.34 175.43,37.12 174.21,37.35 173.09,37.3 172.09,37.25 154.64,36.41 140.77,37.58 131.4,36.78 121.06,37.56 99.59,36.51 92.27,36.98 84.95,37.45 78.24,37.5 78.24,37.5 71.52,37.55 65.12,37.18 59.35,37.57 48.4,37.25 38.8,37.81 37.17,38.34 26.65,44.98 24.56,47.02 24.26,47.47 24.07,48.01 23.6,52.97 23.46,53.38 23.46,53.38 23.41,53.52 23.41,53.52 23.12,54.33 22.55,55.93 22.23,56.85 20.2,59.72 19.58,60.21 18.81,60.52 17.14,60.63 15.81,60.27 14.4,59.34 12.73,58.25 8.81,56.62 8.18,55.99 8.18,54.8 8.51,54.47 8.83,54.47 J9.H2
LAN_SLED3_MDIN0: length 48.1
  IN2 w0.114: J10.B1 231.04,45.16 231.88,45.16 232.44,44.61 232.44,43.21 232.24,42.74 231.7,42.28 229.19,40.13 228.27,39.75 227.06,39.66 221.65,39.24 220.52,38.85 215.53,35.44 211.91,34.46 198.01,33.76 191.38,33.76 J8.K10
LAN_SLED3_MDIN1: length 56.5
  IN2 w0.114: J10.E1 231.04,49.36 233.15,49.36 233.93,48.59 233.93,42.68 233.63,42 233.28,41.7 230.37,39.17 229.91,38.76 229.4,38.55 222.44,38.02 220.88,37.52 216.16,34.3 212.64,33.21 198.52,32.21 192.07,29.53 191.35,29.53 J8.H10
LAN_SLED3_MDIN2: length 62
  IN2 w0.114: J10.H1 230.06,53.56 229.66,53.56 229.28,53.18 229.28,42.98 228.55,42.25 227.25,41.71 222.66,41.33 221.26,40.99 219.64,40.31 214.91,37.22 214.04,36.79 212.28,36.47 208.38,36.2 200.81,36.33 194.03,36.62 191.1,37.12 190.68,37.12 190.23,36.93 189.69,36.39 189.69,28.84 189.55,28.7 189.39,28.7 J8.H9
LAN_SLED3_MDIN3: length 59.6
  IN2 w0.114: J10.I2 228.06,54.86 227.66,54.86 227.28,54.48 227.28,43.57 227,43.26 226.65,43.23 222.23,42.79 219.11,41.5 214,38.19 213.72,38.08 213.44,37.96 212.35,37.77 209.18,37.55 200.89,37.84 200.89,37.84 192.72,38.11 190.99,38.41 189.2,38.28 188.71,37.93 187.69,35.47 187.69,32.85 188.06,32.47 188.41,32.47 J8.J9
LAN_SLED3_MDIP0: length 48.1
  IN2 w0.114: J10.A1 231.04,44.74 231.7,44.74 232.01,44.43 232.01,43.29 231.89,42.99 231.57,42.73 231.28,42.75 231.02,42.53 231,42.24 230.74,42.02 230.45,42.04 230.19,41.82 230.17,41.53 229.91,41.31 229.62,41.33 229.36,41.11 229.34,40.82 228.97,40.5 228.17,40.17 227.2,40.1 226.98,40.29 226.64,40.26 226.45,40.04 226.11,40.01 225.89,40.2 225.55,40.18 225.37,39.96 225.02,39.93 224.81,40.12 224.46,40.09 224.28,39.87 223.93,39.85 223.72,40.03 223.37,40.01 223.19,39.79 222.85,39.76 222.63,39.95 222.29,39.92 222.1,39.71 221.56,39.67 220.32,39.23 215.35,35.83 211.84,34.88 198,34.19 198,34.19 191.39,34.19 J8.L10
LAN_SLED3_MDIP1: length 56.5
  IN2 w0.114: J10.D1 231.04,48.94 232.98,48.94 233.5,48.41 233.5,47.93 233.3,47.73 233.3,47.38 233.5,47.18 233.5,46.84 233.3,46.63 233.3,46.29 233.5,46.09 233.5,45.75 233.3,45.54 233.3,45.2 233.5,45 233.5,44.65 233.3,44.45 233.3,44.11 233.5,43.9 233.5,42.77 233.28,42.26 233,42.02 232.71,42.04 232.45,41.82 232.43,41.53 232.17,41.3 231.89,41.32 231.63,41.1 231.61,40.81 231.35,40.59 231.06,40.61 230.8,40.38 230.78,40.09 230.53,39.87 230.24,39.89 229.98,39.66 229.96,39.38 229.68,39.13 229.29,38.97 222.36,38.45 220.69,37.91 215.97,34.68 212.56,33.64 198.42,32.63 191.99,29.96 191.42,29.96 J8.I10
LAN_SLED3_MDIP2: length 62
  IN2 w0.114: J8.G9 189.39,28.27 189.73,28.27 190.11,28.66 190.11,36.21 190.47,36.57 190.77,36.69 191.06,36.69 193.99,36.19 200.8,35.91 208.39,35.77 212.33,36.05 214.17,36.38 215.12,36.84 219.84,39.93 221.39,40.58 222.73,40.9 227.35,41.29 228.06,41.59 228.79,41.89 229.71,42.8 229.71,53 229.84,53.14 230.06,53.14 J10.G1
LAN_SLED3_MDIP3: length 59.7
  IN2 w0.114: J8.K9 188.41,32.9 188.24,32.9 188.11,33.02 188.11,35.39 188.24,35.7 188.51,35.81 188.64,36.13 188.53,36.39 188.66,36.71 188.93,36.82 189.06,37.14 188.95,37.4 189.05,37.65 189.35,37.87 190.97,37.98 192.67,37.69 196.85,37.55 197.05,37.34 197.39,37.32 197.6,37.52 197.95,37.51 198.14,37.3 198.48,37.29 198.69,37.48 199.04,37.47 199.23,37.26 199.58,37.25 199.79,37.45 200.13,37.43 200.32,37.22 200.67,37.21 200.88,37.41 209.19,37.13 212.4,37.35 213.56,37.55 214.2,37.81 219.31,41.12 222.34,42.38 222.96,42.44 222.96,42.44 223.12,42.31 223.46,42.34 223.58,42.5 223.92,42.53 224.08,42.41 224.42,42.44 224.54,42.59 224.89,42.63 225.04,42.5 225.38,42.53 225.51,42.69 226.05,42.74 226.21,42.6 226.56,42.64 226.7,42.8 226.7,42.81 227.2,42.85 227.71,43.41 227.71,54.31 227.84,54.44 228.06,54.44 J10.H2
PD_BBU_A0: length 19.7
  TOP w0.114: R31.2 R32.1 212.39,23.65 v1(212.8,24.06) 214.41,24.06 215.97,22.49 215.97,19.5 219.59,15.89 219.59,12.26 J7.H6
PD_SLED1_CHASSIS_INTRUSION: length 29
  TOP w0.114: R54.1 207.87,26.95 v1(207.87,26.95)
  IN1 w0.127: J7.H4 225.32,12.07 225.32,14.16 216.45,23.04 216.45,24.23 215.23,25.44 215.23,26.2 213.18,28.25 209.18,28.25 v1(207.87,26.95)
PD_SLED1_PRSNT_RETURN: length 71
  TOP w0.114: R41.1 166.93,34.13 169.99,31.07 169.99,28.09 171.01,27.07 175.56,27.07 175.84,26.79 175.84,23.61 176.6,22.85 189.61,22.85 190.03,23.27 190.03,23.9 190.25,24.12 196.01,24.12 v1(197.04,23.09)
  IN1 w0.127: v1(197.04,23.09) 198.18,21.95 214.1,21.95 220.55,15.5 J7.I6
PD_SLED2_CHASSIS_INTRUSION: length 18
  TOP w0.114: J9.H4 4.46,53.06 4.46,42.23 7.62,39.07 7.63,39.07 R55.1
PD_SLED2_PRSNT_RETURN: length 181.9
  TOP w0.114: R42.1 153.74,34.28 150.94,31.48 150.94,30.77 v1(150.25,30.08)
  IN1 w0.127: v1(150.25,30.08) 150.25,30.53 146.53,34.25 40.5,34.25 v1(39,32.75)
  BOTTOM w0.114: J9.I6 2.34,54.36 2.34,40.25 5.5,37.08 6.29,37.08 10.07,33.3 15.77,33.3 19.72,37.25 24.32,37.25 25.9,36.59 31.56,30.94 36.72,30.94 38.54,32.75 v1(39,32.75)
PD_SLED3_CHASSIS_INTRUSION: length 8.1
  TOP w0.114: J10.H4 225.58,54.98 225.58,58.9 v1(226.67,59.99) R56.1
PD_SLED3_PRSNT_RETURN: length 94.8
  TOP w0.114: v1(194.67,29.12) 192.55,31.24 190.2,31.24 189.84,30.88 189.84,30.24 189.52,29.91 187.94,29.91 187.76,29.73 186.56,29.73 185.87,29.04 185.87,26.25 185.36,25.73 184.5,25.73 183.99,25.23 183.99,24.62 183.61,24.24 182.54,24.24 182.16,24.61 182.16,26.09 181.19,27.07 176.63,27.07 175.28,28.42 171.72,28.42 170.41,29.74 170.41,31.37 166.22,35.56 R43.1 ; J10.I6 219.3,54.1 219.3,30.53 218.27,29.5 v1(215.48,29.5)
  IN2 w0.127: v1(215.48,29.5) 212.28,29.5 209.94,27.16 208.43,27.16 206.36,29.23 204.87,29.23 204.28,28.63 195.16,28.63 v1(194.67,29.12)
SB_SLED1_ADDR_0: length 41.6
  TOP w0.114: J7.B2 229.82,4.17 229.82,13.71 227.69,15.84 224.81,15.84 220.79,19.86 220.79,25.2 217.86,28.14 v1(215.25,28.14) 214.84,28.14 R2297.2 R2298.1
SB_SLED1_ADDR_1: length 38.9
  TOP w0.114: R13.2 R21.1 212.11,29.74 214.37,27.48 v1(216.64,27.48) 218.14,27.48 220.53,25.09 220.53,19.75 224.7,15.58 227.58,15.58 229.56,13.6 229.56,5.31 J7.C2
SB_SLED1_ADDR_2: length 34.8
  TOP w0.114: J7.E2 229.29,7.84 229.29,13.49 227.47,15.31 224.59,15.31 220.03,19.87 v1(220.03,20.85) 220.03,25.21 218.22,27.02 213.84,27.02 213.15,27.71 R15.2 R24.1
SB_SLED2_ADDR_0: length 21.4
  TOP w0.114: R9.1 R8.2 13.59,58.79 v1(12.12,58.79) 10.62,57.29 10.62,46.82 J9.B2
SB_SLED2_ADDR_1: length 19.1
  TOP w0.114: J9.C2 10.36,47.96 10.36,57.74 11.87,59.25 13.34,59.25 14.73,60.64 v1(14.73,61.3) R19.1 R1.2
SB_SLED2_ADDR_2: length 15
  TOP w0.114: R14.2 R22.1 13.72,61.5 v1(13.15,60.94) 10.09,57.87 10.09,50.49 J9.E2
SB_SLED3_ADDR_0: length 18.4
  TOP w0.114: R10.2 R11.1 232.85,59.15 v1(232.39,58.7) 229.81,56.11 229.81,46.81 J10.B2
SB_SLED3_ADDR_1: length 16.1
  TOP w0.114: J10.C2 229.41,47.81 229.41,58.54 v1(230.73,59.86) R12.2 R20.1
SB_SLED3_ADDR_2: length 13.2
  TOP w0.114: J10.E2 227.69,50.61 227.69,58.32 v1(228.7,59.33) R2.2 R23.1
SMB_3UBP_TEMP_SCL: length 141.9
  TOP w0.114: R1123.1 v1(153.28,27.43) ; U31.2 38.91,21.22 38.25,21.87 36.45,21.87 v3(36.1,22.22) 35.75,21.87 34.87,21.87 34.43,22.31 34.43,29.09 v1(35.16,29.82)
  IN1 w0.127: v1(35.16,29.82) 35.85,30.51 35.85,32.77 38.96,35.88 147.51,35.88 152.38,31.01 152.38,28.33 v1(153.28,27.43)
SMB_3UBP_TEMP_SDA: length 4
  TOP w0.114: R1122.1 v3(36.08,20.75) 36.6,20.75 37.08,21.24 37.45,21.24 37.64,21.05 U31.1
SMB_BBU_ALERT_N: length 54.9
  TOP w0.114: R37.2 211.2,21.2 211.05,21.05 210.85,21.05 R38.1 209.79,20.6 206.26,24.14 206.26,24.98 v1(206.26,26.75)
  IN1 w0.127: J8.A7 183.68,20.61 183.68,35.23 186.02,37.57 192.63,37.57 197.36,32.84 197.36,31.33 201.41,27.27 205.74,27.27 v1(206.26,26.75)
SMB_BBU_ALERT_R_N: length 21.7
  TOP w0.114: v1(213.24,16.54) 213.24,19.1 211.75,20.6 R38.2
  BOTTOM w0.114: v1(213.24,16.54) 215.37,14.41 220.45,14.41 221.78,13.07 221.78,8.33 J7.E6
SMB_PMBUS_BBU_SCL: length 46.2
  TOP w0.114: v1(214.28,25.66) 215.58,25.66 216.76,24.48 216.76,19.85 221.8,14.81 221.8,4.15 J7.B6 ; v1(202.68,25.65) 202.4,25.37 197.99,25.37 R39.2
  BOTTOM w0.114: v1(214.28,25.66) 213.32,25.66 210.47,22.8 205.47,22.8 202.68,25.59 v1(202.68,25.65)
SMB_PMBUS_BBU_SDA: length 42.6
  TOP w0.114: R40.2 198.42,26.63 198.71,26.92 v1(199.21,26.92) ; J7.C6 221.39,5.14 221.39,14.64 216.37,19.67 216.37,23.56 v1(215.26,24.66) 209.73,24.66 v1(208.59,25.81)
  BOTTOM w0.114: v1(208.59,25.81) 208.25,26.15 205.6,26.15 205.49,26.26 205.49,26.95 204.97,27.47 199.82,27.47 199.27,26.92 v1(199.21,26.92)
SMB_PMBUS_SCL: length 15.1
  TOP w0.114: R39.1 196.98,25.58 v3(195.14,25.58) 193.65,27.06 190.28,27.06 189.89,26.66 189.89,26.26 189.37,25.74 188.02,25.74 187.9,25.63 187.9,24.53 187.46,24.09 186.03,24.09 185.53,23.58 J8.D7
SMB_PMBUS_SDA: length 14.4
  TOP w0.114: R40.1 195.88,27.76 v3(194.89,27.76) 194.36,28.29 190.34,28.29 189.93,27.88 189.93,27.43 189.53,27.03 188.58,27.03 187.2,25.65 186.34,25.65 185.67,24.98 J8.E7
SMB_SLED_BUF_SCL: length 121.5
  TOP w0.114: v1(200.65,22.57) 199.83,21.74 194.59,21.74 191.51,18.66 171.9,18.66 170.87,19.69 170.87,22.55 168.4,25.02 168.4,29.05 167.28,30.17 R52.2 166.21,29.73 166.45,29.48 R3.1
  IN1 w0.127: v1(200.65,22.57) 214.3,22.57 221.36,15.5 221.36,11.19 J7.G5
  BOTTOM w0.114: J10.G5 221.75,51.85 221.75,40.81 211.2,30.27 211.2,26.13 209.67,24.6 204.89,24.6 203.23,26.26 202.3,26.26 200.65,24.61 v1(200.65,22.57)
SMB_SLED_BUF_SCL_R: length 5.4
  TOP w0.114: R50.2 165.35,29.79 165.41,29.84 R52.1 164.67,30.17 v3(163.81,29.31) 163.28,29.31 163.16,29.43 U118.2
SMB_SLED_BUF_SCL_R1: length 187.2
  TOP w0.114: R3.2 167.05,28.31 v1(167.32,28.57)
  IN1 w0.127: v1(37.63,32.82) 39.82,35.01 147.15,35.01 151.4,30.77 151.4,27.57 152.6,26.37 164.28,26.37 166.49,28.57 v1(167.32,28.57)
  BOTTOM w0.114: v1(37.63,32.82) 37.63,32.42 36.54,31.33 31.74,31.33 26.03,37.03 24.52,37.66 16.93,37.66 14.61,39.98 6.73,39.98 4.15,42.56 4.15,51.85 J9.G5
SMB_SLED_BUF_SDA: length 307.2
  TOP w0.114: v1(199.92,22.57) 199.62,22.26 192.81,22.26 192.23,22.84 190.21,22.84 189.93,22.55 189.93,22.02 189.39,21.49 176.51,21.49 176.1,21.89 176.1,22.33 175.62,22.82 171.31,22.82 168.96,25.16 168.96,29.22 v1(168.4,29.79) 166.98,31.21 R53.2
  IN1 w0.127: v1(199.92,22.57) 200.43,23.07 214.4,23.07 221.79,15.68 221.79,12.16 J7.H5 ; v1(168.4,29.79) 163.92,29.79 160.95,26.81 152.9,26.81 151.88,27.84 151.88,30.9 147.33,35.44 39.56,35.44 v1(36.92,32.8)
  BOTTOM w0.114: J9.H5 4.62,52.78 4.62,43.74 7.93,40.43 14.76,40.43 17.12,38.08 24.56,38.08 26.28,37.37 31.92,31.72 36.38,31.72 36.92,32.27 v1(36.92,32.8) ; J10.H5 221.35,52.85 221.35,40.98 210.8,30.43 210.8,26.29 209.51,24.99 205.25,24.99 203.43,26.81 201.77,26.81 199.92,24.97 v1(199.92,22.57)
SMB_SLED_BUF_SDA_R: length 6.1
  TOP w0.114: U118.3 163.23,30.08 163.73,30.58 163.73,31.44 164.55,31.44 164.79,31.21 R53.1 R51.2
SMB_SLED_COMBINE_SCL: length 17.4
  TOP w0.114: R46.1 153.55,29.19 R1123.2 152.98,29.22 v1(152.98,30.51) ; R4.1 164.5,25.94 v1(162.89,27.55)
  IN2 w0.127: v1(162.89,27.55) 159.61,30.83 153.31,30.83 v1(152.98,30.51)
SMB_SLED_COMBINE_SCL_R: length 4.3
  TOP w0.114: R48.2 R46.2 154.74,29.94 155.58,29.11 156.11,29.11 156.43,29.43 U118.7
